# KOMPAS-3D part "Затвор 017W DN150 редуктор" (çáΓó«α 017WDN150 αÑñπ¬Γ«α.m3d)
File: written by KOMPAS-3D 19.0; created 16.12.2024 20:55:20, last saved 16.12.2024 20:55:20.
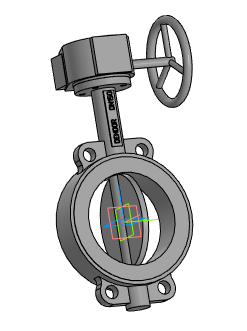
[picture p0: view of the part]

Document properties: Автор: Евгений; Полное имя файла: ..\Затвор 017WDN150 редуктор.a3d

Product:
- Part/product: Затвор 017W DN150 редуктор
    Масса: 18.2186

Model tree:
1. Операция без истории:1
